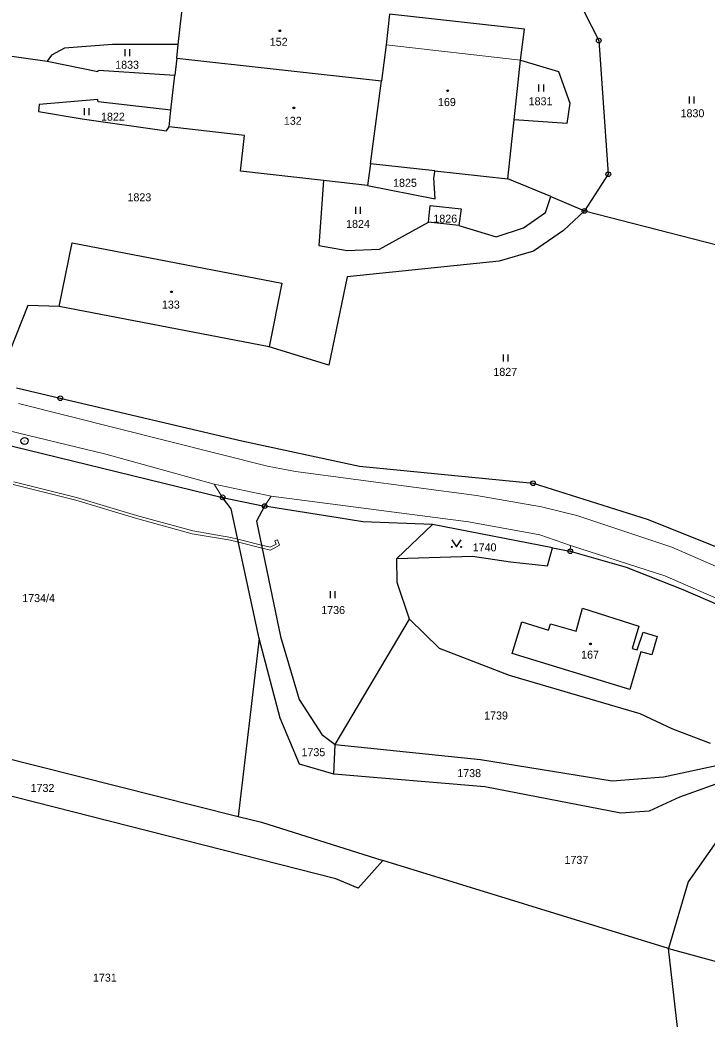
# Model space of a CAD drawing. Extents: x -601131 to -597152, y -1058536 to -1055911.
# Drawn here: x -599212.3 to -599066.3, y -1057278.4 to -1057066.1 of the extents above; entities that cross this region are included whole.
import ezdxf
from ezdxf.enums import TextEntityAlignment as Align

# ---------------------------------------------------------------- set-up
doc = ezdxf.new("R2010")
doc.units = 0
doc.header["$LTSCALE"] = 0.68
for name, color, linetype, lineweight in [('1', 7, 'Continuous', 25), ('13', 7, 'Continuous', 13), ('3', 7, 'Continuous', 25), ('4', 7, 'Continuous', 13), ('5', 7, 'Continuous', 25), ('8', 7, 'Continuous', 25)]:
    doc.layers.add(name, color=color, linetype=linetype, lineweight=lineweight)
doc.layers.add('2', color=7, linetype='Continuous')

msp = doc.modelspace()

# ---------------------------------------------------------------- linework, layer by layer
at = {"layer": '1'}
for p, q in [((-599178.66, -1057071.37), (-599177.41, -1057060)), ((-599094.31, -1057060.61), (-599089.27, -1057070.52)), ((-599133.73, -1057064.9), (-599134.46, -1057071.44)), ((-599105.08, -1057068.07), (-599133.73, -1057064.9)), ((-599105.88, -1057074.69), (-599105.08, -1057068.07)), ((-599089.27, -1057070.52), (-599087.24, -1057098.91)), ((-599220.11, -1057072.92), (-599206.53, -1057074.91)), ((-599202.84, -1057072.11), (-599205.55, -1057073.58)), ((-599192.6, -1057071.34), (-599202.84, -1057072.11)), ((-599178.66, -1057071.37), (-599192.6, -1057071.34)), ((-599178.97, -1057074.24), (-599178.66, -1057071.37)), ((-599134.46, -1057071.44), (-599135.47, -1057079.09)), ((-599205.55, -1057073.58), (-599206.53, -1057074.91)), ((-599206.53, -1057074.91), (-599195.76, -1057077.1)), ((-599178.97, -1057074.24), (-599179.37, -1057077.87)), ((-599178.97, -1057074.24), (-599135.47, -1057079.09)), ((-599107.26, -1057087.35), (-599105.88, -1057074.69)), ((-599105.88, -1057074.69), (-599097.82, -1057077.04)), ((-599195.76, -1057077.1), (-599195.57, -1057076.82)), ((-599195.57, -1057076.82), (-599179.37, -1057077.87)), ((-599097.82, -1057077.04), (-599095.4, -1057083.83)), ((-599180.19, -1057085.31), (-599179.37, -1057077.87)), ((-599137.8, -1057096.66), (-599135.47, -1057079.09)), ((-599195.7, -1057083), (-599208.2, -1057084.09)), ((-599195.66, -1057083.55), (-599195.7, -1057083)), ((-599180.19, -1057085.31), (-599195.66, -1057083.55)), ((-599208.2, -1057084.09), (-599208.35, -1057085.59)), ((-599208.35, -1057085.59), (-599199.07, -1057087.16)), ((-599180.58, -1057088.86), (-599180.19, -1057085.31)), ((-599095.4, -1057083.83), (-599096.05, -1057088.15)), ((-599199.07, -1057087.16), (-599181.12, -1057089.66)), ((-599108.62, -1057099.87), (-599107.26, -1057087.35)), ((-599096.05, -1057088.15), (-599107.26, -1057087.35)), ((-599181.12, -1057089.66), (-599180.58, -1057088.86)), ((-599164.53, -1057090.66), (-599180.58, -1057088.86)), ((-599165.39, -1057098.25), (-599164.53, -1057090.66)), ((-599147.78, -1057100.23), (-599165.39, -1057098.25)), ((-599137.8, -1057096.66), (-599138.41, -1057101.29)), ((-599124.09, -1057098.17), (-599137.8, -1057096.66)), ((-599124.18, -1057098.99), (-599124.09, -1057098.17)), ((-599124.09, -1057098.17), (-599108.62, -1057099.87)), ((-599147.78, -1057100.23), (-599148.76, -1057114.01)), ((-599138.41, -1057101.29), (-599147.78, -1057100.23)), ((-599124.29, -1057099.63), (-599124.18, -1057098.99)), ((-599124.07, -1057104.14), (-599124.29, -1057099.63)), ((-599099.46, -1057103.61), (-599108.62, -1057099.87)), ((-599087.24, -1057098.91), (-599092.31, -1057106.69)), ((-599138.41, -1057101.29), (-599124.07, -1057104.14)), ((-599100.59, -1057107), (-599099.46, -1057103.61)), ((-599099.46, -1057103.61), (-599092.31, -1057106.69)), ((-599125.48, -1057109.06), (-599125.07, -1057105.52)), ((-599125.07, -1057105.52), (-599118.53, -1057106.27)), ((-599118.53, -1057106.27), (-599119.01, -1057109.82)), ((-599105.26, -1057110.32), (-599100.59, -1057107)), ((-599092.31, -1057106.69), (-599096.79, -1057110.88)), ((-599092.31, -1057106.69), (-599055.36, -1057116.14)), ((-599135.9, -1057114.84), (-599125.48, -1057109.06)), ((-599119.01, -1057109.82), (-599125.48, -1057109.06)), ((-599119.01, -1057109.82), (-599111.07, -1057112.22)), ((-599111.07, -1057112.22), (-599105.26, -1057110.32)), ((-599096.79, -1057110.88), (-599103.11, -1057115.25)), ((-599148.76, -1057114.01), (-599142.76, -1057115.09)), ((-599142.76, -1057115.09), (-599135.9, -1057114.84)), ((-599103.11, -1057115.25), (-599110.43, -1057117.37)), ((-599110.43, -1057117.37), (-599142.73, -1057120.71)), ((-599142.73, -1057120.71), (-599146.62, -1057139.46)), ((-599156.61, -1057122.04), (-599159.32, -1057135.58)), ((-599210.61, -1057126.79), (-599215.7, -1057139.66)), ((-599203.92, -1057127), (-599210.61, -1057126.79)), ((-599159.32, -1057135.58), (-599203.92, -1057127)), ((-599146.62, -1057139.46), (-599159.32, -1057135.58)), ((-599212.99, -1057144.29), (-599203.71, -1057146.48)), ((-599203.71, -1057146.48), (-599165.1, -1057155.51)), ((-599217.43, -1057155.81), (-599169.22, -1057167.54)), ((-599165.1, -1057155.51), (-599140.12, -1057160.91)), ((-599140.12, -1057160.91), (-599103.22, -1057164.55)), ((-599103.22, -1057164.55), (-599078.99, -1057172.16)), ((-599167.37, -1057169.97), (-599169.22, -1057167.54)), ((-599169.22, -1057167.54), (-599160.28, -1057169.39)), ((-599161.41, -1057197.56), (-599167.37, -1057169.97)), ((-599160.28, -1057169.39), (-599162.03, -1057172.6)), ((-599144.62, -1057171.9), (-599160.28, -1057169.39)), ((-599162.03, -1057172.6), (-599156.92, -1057197.13)), ((-599139.39, -1057172.74), (-599144.62, -1057171.9)), ((-599124.58, -1057173.32), (-599139.39, -1057172.74)), ((-599078.99, -1057172.16), (-599046.11, -1057185.36)), ((-599124.58, -1057173.32), (-599132.16, -1057180.56)), ((-599099.07, -1057178.26), (-599124.58, -1057173.32)), ((-599100.17, -1057182.09), (-599099.07, -1057178.26)), ((-599099.07, -1057178.26), (-599095.32, -1057178.99)), ((-599095.32, -1057178.99), (-599083.43, -1057182.39)), ((-599132.16, -1057180.56), (-599116.12, -1057180.01)), ((-599132.09, -1057185.6), (-599132.16, -1057180.56)), ((-599116.12, -1057180.01), (-599108.01, -1057181.24)), ((-599108.01, -1057181.24), (-599100.17, -1057182.09)), ((-599083.43, -1057182.39), (-599071.38, -1057187.1)), ((-599129.48, -1057193.39), (-599132.09, -1057185.6)), ((-599071.38, -1057187.1), (-599061.43, -1057191.48)), ((-599094.08, -1057195.98), (-599092.7, -1057191.1)), ((-599092.7, -1057191.1), (-599080.73, -1057194.89)), ((-599145.32, -1057220.05), (-599129.48, -1057193.39)), ((-599129.48, -1057193.39), (-599123.16, -1057199.57)), ((-599107.65, -1057200.74), (-599105.64, -1057193.96)), ((-599105.64, -1057193.96), (-599099.93, -1057195.75)), ((-599099.93, -1057195.75), (-599099.5, -1057194.39)), ((-599099.5, -1057194.39), (-599094.08, -1057195.98)), ((-599080.73, -1057194.89), (-599082.15, -1057199.63)), ((-599161.41, -1057197.56), (-599165.88, -1057235.34)), ((-599156.96, -1057214.48), (-599161.41, -1057197.56)), ((-599156.92, -1057197.13), (-599152.95, -1057210.51)), ((-599081.08, -1057199.96), (-599079.82, -1057196.21)), ((-599079.82, -1057196.21), (-599076.87, -1057197.08)), ((-599076.87, -1057197.08), (-599077.99, -1057201.02)), ((-599123.16, -1057199.57), (-599108.32, -1057205.28)), ((-599080.31, -1057200.34), (-599082.67, -1057208.35)), ((-599082.15, -1057199.63), (-599081.08, -1057199.96)), ((-599077.99, -1057201.02), (-599080.31, -1057200.34)), ((-599082.67, -1057208.35), (-599107.65, -1057200.74)), ((-599108.32, -1057205.28), (-599080.55, -1057213.47)), ((-599152.95, -1057210.51), (-599148.1, -1057217.93)), ((-599152.88, -1057224.22), (-599156.96, -1057214.48)), ((-599080.55, -1057213.47), (-599073.57, -1057216.7)), ((-599073.57, -1057216.7), (-599065.61, -1057219.78)), ((-599236.94, -1057217.47), (-599165.88, -1057235.34)), ((-599148.1, -1057217.93), (-599145.32, -1057220.05)), ((-599145.55, -1057226.33), (-599145.32, -1057220.05)), ((-599145.32, -1057220.05), (-599114.44, -1057223.2)), ((-599114.44, -1057223.2), (-599086.44, -1057227.73)), ((-599047.32, -1057222.32), (-599072.12, -1057231.26)), ((-599145.12, -1057248.56), (-599238.44, -1057224.85)), ((-599145.55, -1057226.33), (-599152.88, -1057224.22)), ((-599075.51, -1057226.92), (-599063.01, -1057224.25)), ((-599113.46, -1057229.05), (-599145.55, -1057226.33)), ((-599086.44, -1057227.73), (-599075.51, -1057226.92)), ((-599084.55, -1057234.63), (-599113.46, -1057229.05)), ((-599072.12, -1057231.26), (-599078.53, -1057234.23)), ((-599078.53, -1057234.23), (-599084.55, -1057234.63)), ((-599165.88, -1057235.34), (-599160.97, -1057236.57)), ((-599160.97, -1057236.57), (-599135.13, -1057244.72)), ((-599064.24, -1057240.63), (-599070.25, -1057249.23)), ((-599135.13, -1057244.72), (-599140.41, -1057250.58)), ((-599074.47, -1057263.35), (-599135.13, -1057244.72)), ((-599140.41, -1057250.58), (-599145.12, -1057248.56)), ((-599070.25, -1057249.23), (-599074.47, -1057263.35)), ((-599071.62, -1057287.83), (-599074.47, -1057263.35)), ((-599074.47, -1057263.35), (-598958.96, -1057295.03))]:
    msp.add_line(p, q, dxfattribs=at)
msp.add_lwpolyline([(-599203.92, -1057127), (-599201.16, -1057113.48), (-599156.61, -1057122.04)], dxfattribs=at)
at = {"layer": '13'}
msp.add_lwpolyline([(-599213.73, -1057164.82), (-599200.43, -1057168.16), (-599187.7, -1057171.98), (-599175.66, -1057175.26), (-599167.55, -1057176.66), (-599165.83, -1057177.09), (-599165.97, -1057176.44), (-599167.43, -1057176.08), (-599175.52, -1057174.68), (-599187.54, -1057171.4), (-599200.27, -1057167.58), (-599213.59, -1057164.24)], dxfattribs=at)
msp.add_lwpolyline([(-599165.97, -1057176.44), (-599165.83, -1057177.09), (-599160.84, -1057178.33), (-599159.05, -1057178.77), (-599157.1, -1057177.73), (-599157.52, -1057176.55), (-599158.08, -1057176.75), (-599157.84, -1057177.45), (-599159.13, -1057178.13), (-599160.97, -1057177.67)], close=True, dxfattribs=at)
at = {"layer": '3'}
for p, q in [((-599189.941, -1057073.85), (-599189.941, -1057072.35)), ((-599188.94, -1057073.85), (-599188.94, -1057072.35)), ((-599101.981, -1057081.31), (-599101.981, -1057079.81)), ((-599100.98, -1057081.31), (-599100.98, -1057079.81)), ((-599069.981, -1057083.9), (-599069.981, -1057082.4)), ((-599068.98, -1057083.9), (-599068.98, -1057082.4)), ((-599198.591, -1057086.34), (-599198.591, -1057084.84)), ((-599197.59, -1057086.34), (-599197.59, -1057084.84)), ((-599140.881, -1057107.32), (-599140.881, -1057105.82)), ((-599139.88, -1057107.32), (-599139.88, -1057105.82)), ((-599109.551, -1057138.7), (-599109.551, -1057137.2)), ((-599108.55, -1057138.7), (-599108.55, -1057137.2)), ((-599146.311, -1057188.95), (-599146.311, -1057187.45)), ((-599145.31, -1057188.95), (-599145.31, -1057187.45))]:
    msp.add_line(p, q, dxfattribs=at)
msp.add_lwpolyline([(-599120.51, -1057176.579), (-599119.51, -1057178.08), (-599118.51, -1057176.579)], dxfattribs=at)
for centre in [(-599120.51, -1057178.0795), (-599118.51, -1057178.0795)]:
    msp.add_circle(centre, 0.1, dxfattribs=at)
at = {"layer": '4'}
for p, q in [((-599105.88, -1057074.69), (-599134.46, -1057071.44)), ((-599159.66, -1057160.88), (-599212.59, -1057147.63)), ((-599221.22, -1057151.81), (-599194.02, -1057158.4)), ((-599194.02, -1057158.4), (-599170.98, -1057164.71)), ((-599153.73, -1057162.03), (-599159.66, -1057160.88)), ((-599153.73, -1057162.03), (-599115.28, -1057167.17)), ((-599170.98, -1057164.71), (-599158.86, -1057167.29)), ((-599169.22, -1057167.54), (-599170.98, -1057164.71)), ((-599158.86, -1057167.29), (-599160.28, -1057169.39)), ((-599116.96, -1057172.75), (-599158.86, -1057167.29)), ((-599115.28, -1057167.17), (-599101.43, -1057169.53)), ((-599101.43, -1057169.53), (-599093.95, -1057171.42)), ((-599101.82, -1057175.48), (-599116.96, -1057172.75)), ((-599093.95, -1057171.42), (-599073.77, -1057178.15)), ((-599095.29, -1057177.74), (-599101.82, -1057175.48)), ((-599095.29, -1057177.74), (-599095.32, -1057178.99)), ((-599075.24, -1057184.2), (-599095.29, -1057177.74)), ((-599073.77, -1057178.15), (-599053.81, -1057186.85)), ((-599056.26, -1057192.48), (-599075.24, -1057184.2))]:
    msp.add_line(p, q, dxfattribs=at)
at = {"layer": '5'}
for centre in [(-599157.0668, -1057068.4192), (-599121.3668, -1057081.1692), (-599154.0668, -1057084.7992), (-599180.0868, -1057123.8792), (-599091.0368, -1057198.6692)]:
    msp.add_circle(centre, 0.175, dxfattribs=at)
at = {"layer": '8'}
for centre, radius in [((-599089.27, -1057070.5199), 0.5), ((-599089.27, -1057070.5199), 0.0303), ((-599087.24, -1057098.9099), 0.5), ((-599087.24, -1057098.9099), 0.0303), ((-599092.31, -1057106.6899), 0.5), ((-599092.31, -1057106.6899), 0.0303), ((-599203.71, -1057146.4799), 0.5), ((-599203.71, -1057146.4799), 0.0303), ((-599211.31, -1057155.5598), 0.75), ((-599211.31, -1057155.5598), 0.03), ((-599103.22, -1057164.5499), 0.5), ((-599103.22, -1057164.5499), 0.0303), ((-599169.22, -1057167.5399), 0.5), ((-599169.22, -1057167.5399), 0.0303), ((-599160.28, -1057169.3899), 0.5), ((-599160.28, -1057169.3899), 0.0303), ((-599095.32, -1057178.9899), 0.5), ((-599095.32, -1057178.9899), 0.0303)]:
    msp.add_circle(centre, radius, dxfattribs=at)

# ---------------------------------------------------------------- texts
at = {"layer": '2'}
for s, p in [('152', (-599157.289, -1057071.615)), ('1833', (-599189.51, -1057076.492)), ('169', (-599121.549, -1057084.422)), ('1831', (-599101.64, -1057084.252)), ('1830', (-599069.36, -1057086.792)), ('1822', (-599192.52, -1057087.522)), ('132', (-599154.299, -1057088.392)), ('1825', (-599130.45, -1057101.572)), ('1823', (-599186.9, -1057104.642)), ('1824', (-599140.44, -1057110.302)), ('1826', (-599121.89, -1057109.182)), ('133', (-599180.209, -1057127.442)), ('1827', (-599109.14, -1057141.732)), ('1740', (-599113.53, -1057179.012)), ('1734/4', (-599208.32, -1057189.795)), ('1736', (-599145.72, -1057192.332)), ('167', (-599091.129, -1057201.802)), ('1739', (-599111.11, -1057214.732)), ('1735', (-599149.92, -1057222.522)), ('1738', (-599116.82, -1057226.972)), ('1732', (-599207.49, -1057230.122)), ('1737', (-599094.02, -1057245.412)), ('1731', (-599194.23, -1057270.422))]:
    msp.add_text(s, height=1.7, dxfattribs=at).set_placement(p, align=Align.CENTER)

doc.saveas('drawing.dxf')
